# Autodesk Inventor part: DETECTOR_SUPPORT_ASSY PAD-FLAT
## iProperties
Shininess: 64.0
Length Units: 11272
Angle Units: 11279
Time Units: 11290
Mass Units: 11286
Length Display Precision: 3
Angle Display Precision: 2
Compacted: True
Part Number: DETECTOR_SUPPORT_ASSY PAD-FLAT
Document SubType Name: Modeling
Created: 2004-08
Designer: John Blackburn
Material: STAINLESS_STEEL, AUSTENITIC
Manufacturer: Standard
Standards Organization: Custom
Density: 0.0
Volumn: 0.0
Area: 0.0
PropertySet Name: Model Information
Control State: 0
Master: False
Checked Out: False
Author: John Blackburn
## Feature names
1. ExtrusionBlind1
2. Hole1
3. Rectangular Pattern1
